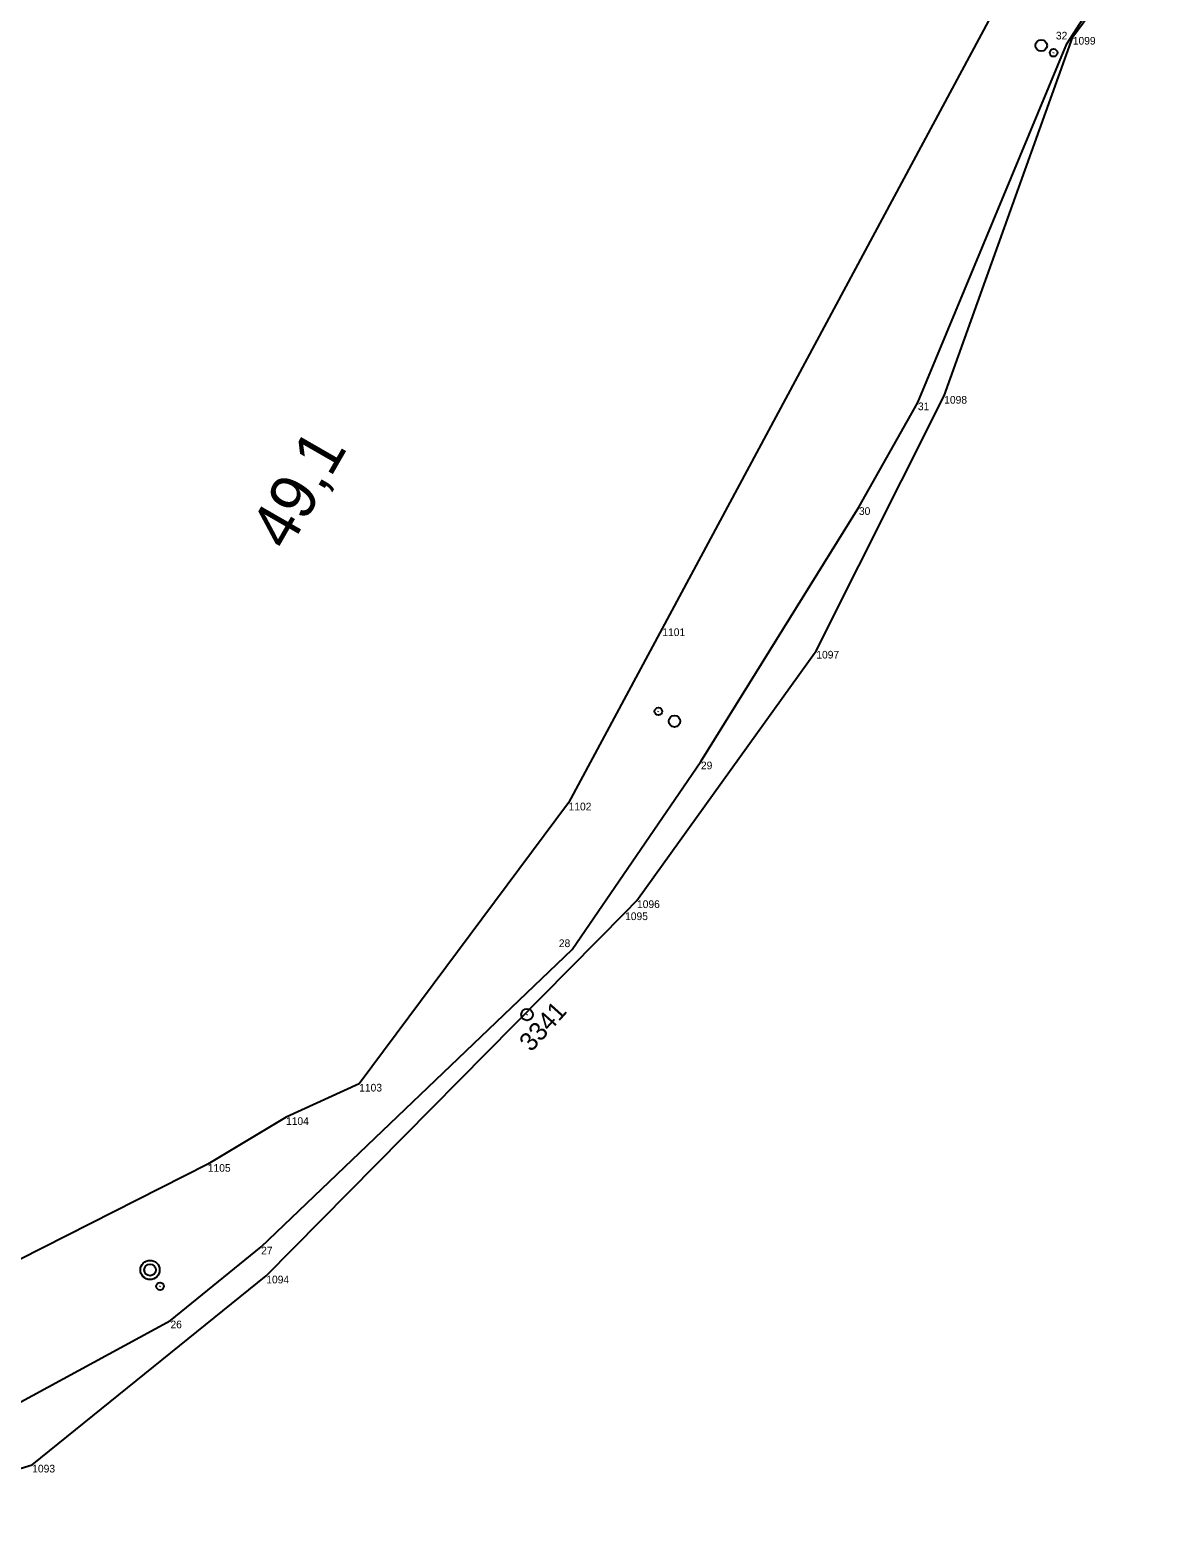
# Model space of a CAD drawing. Extents: x -678683 to -677755, y -1006946 to -1005971.
# Drawn here: x -678536.7 to -678391.2, y -1006829.9 to -1006633.5 of the extents above; entities that cross this region are included whole.
import ezdxf

# ---------------------------------------------------------------- set-up
doc = ezdxf.new("R2010")
doc.units = 0
for name, color, linetype in [('SSZT nové - lomové body', 7, 'Continuous'), ('SSZT_nové', 7, 'Continuous'), ('Stávající ŽBP', 7, 'Continuous'), ('SŽDC', 7, 'Continuous'), ('SŽDC - body', 7, 'Continuous'), ('Vrstva 7', 7, 'Continuous')]:
    doc.layers.add(name, color=color, linetype=linetype)

msp = doc.modelspace()

# ---------------------------------------------------------------- linework, layer by layer
at = {"layer": 'SSZT nové - lomové body'}
for p, q in [((-678401.67, -1006635.24), (-678401.67, -1006635.24)), ((-678421.07, -1006681.97), (-678421.07, -1006681.97)), ((-678428.75, -1006695.61), (-678428.75, -1006695.61)), ((-678449.33, -1006728.75), (-678449.33, -1006728.75)), ((-678466.12, -1006753.23), (-678466.12, -1006753.23)), ((-678506.62, -1006791.94), (-678506.62, -1006791.94)), ((-678518.43, -1006801.56), (-678518.43, -1006801.56))]:
    msp.add_line(p, q, dxfattribs=at)
at = {"layer": 'SSZT_nové'}
for points in [[(-678506.62, -1006791.94), (-678466.12, -1006753.23), (-678449.33, -1006728.75), (-678428.75, -1006695.61), (-678421.07, -1006681.97), (-678401.67, -1006635.24), (-678393.87, -1006623.11), (-678390.13, -1006617.26), (-678380, -1006603.76), (-678359.84, -1006584.7), (-678339.66, -1006565.68), (-678276.52, -1006503.93), (-678276.52, -1006503.93)], [(-678591.08, -1006829.86), (-678578.56, -1006827.33), (-678548.42, -1006815.94), (-678538.41, -1006812.42), (-678518.43, -1006801.56), (-678506.62, -1006791.94), (-678506.62, -1006791.94)]]:
    msp.add_lwpolyline(points, dxfattribs=at)
at = {"layer": 'Stávající ŽBP'}
msp.add_line((-678472.01, -1006761.74), (-678471.94, -1006761.66), dxfattribs=at)
msp.add_circle((-678471.98, -1006761.7), 0.756, dxfattribs=at)
at = {"layer": 'SŽDC'}
for p, q in [((-678400.89, -1006634.35), (-678396.04, -1006627.76)), ((-678411.85, -1006632.26), (-678454.36, -1006711.39)), ((-678417.64, -1006681.12), (-678400.89, -1006634.35)), ((-678434.3, -1006714.32), (-678417.64, -1006681.12)), ((-678454.36, -1006711.39), (-678466.57, -1006734.1)), ((-678457.66, -1006746.82), (-678434.3, -1006714.32)), ((-678466.57, -1006734.1), (-678493.85, -1006770.72)), ((-678505.95, -1006795.71), (-678459.21, -1006748.39)), ((-678459.21, -1006748.39), (-678457.66, -1006746.82)), ((-678493.85, -1006770.72), (-678503.38, -1006775.08)), ((-678503.38, -1006775.08), (-678513.57, -1006781.17)), ((-678513.57, -1006781.17), (-678541.67, -1006795.44)), ((-678536.44, -1006820.34), (-678505.95, -1006795.71)), ((-678542.33, -1006822.15), (-678536.44, -1006820.34))]:
    msp.add_line(p, q, dxfattribs=at)
at = {"layer": 'SŽDC - body'}
for p, q in [((-678400.89, -1006634.35), (-678400.89, -1006634.35)), ((-678417.64, -1006681.12), (-678417.64, -1006681.12)), ((-678454.36, -1006711.39), (-678454.36, -1006711.39)), ((-678434.3, -1006714.32), (-678434.3, -1006714.32)), ((-678466.57, -1006734.1), (-678466.57, -1006734.1)), ((-678459.21, -1006748.39), (-678459.21, -1006748.39)), ((-678457.66, -1006746.82), (-678457.66, -1006746.82)), ((-678493.85, -1006770.72), (-678493.85, -1006770.72)), ((-678503.38, -1006775.08), (-678503.38, -1006775.08)), ((-678513.57, -1006781.17), (-678513.57, -1006781.17)), ((-678505.95, -1006795.71), (-678505.95, -1006795.71)), ((-678536.44, -1006820.34), (-678536.44, -1006820.34))]:
    msp.add_line(p, q, dxfattribs=at)
at = {"layer": 'Vrstva 7'}
for p, q in [((-678403.41, -1006636.46), (-678403.36, -1006636.38)), ((-678454.89, -1006722.25), (-678454.84, -1006722.17)), ((-678519.82, -1006797.1), (-678519.73, -1006797.05))]:
    msp.add_line(p, q, dxfattribs=at)
for centre, radius in [((-678405, -1006635.46), 0.75), ((-678403.39, -1006636.42), 0.5), ((-678454.87, -1006722.21), 0.5), ((-678452.78, -1006723.49), 0.75), ((-678521.09, -1006794.96), 1.25), ((-678521.09, -1006794.96), 0.752), ((-678519.78, -1006797.08), 0.5)]:
    msp.add_circle(centre, radius, dxfattribs=at)

# ---------------------------------------------------------------- texts
at = {"layer": 'SSZT nové - lomové body'}
for s, p in [('32', (-678403.09, -1006634.68)), ('31', (-678421.07, -1006682.97)), ('30', (-678428.75, -1006696.61)), ('29', (-678449.33, -1006729.75)), ('28', (-678467.84, -1006752.91)), ('27', (-678506.62, -1006792.94)), ('26', (-678518.43, -1006802.56))]:
    msp.add_text(s, height=1, dxfattribs=at).set_placement(p)
at = {"layer": 'Stávající ŽBP'}
msp.add_text('3341', height=2.4, rotation=48.0148, dxfattribs=at).set_placement((-678471.44, -1006766.66))
at = {"layer": 'SŽDC - body'}
for s, p in [('1099', (-678400.89, -1006635.35)), ('1098', (-678417.64, -1006682.12)), ('1101', (-678454.36, -1006712.39)), ('1097', (-678434.3, -1006715.32)), ('1102', (-678466.57, -1006735.1)), ('1095', (-678459.21, -1006749.39)), ('1096', (-678457.66, -1006747.82)), ('1103', (-678493.85, -1006771.72)), ('1104', (-678503.38, -1006776.08)), ('1105', (-678513.57, -1006782.17)), ('1094', (-678505.95, -1006796.71)), ('1093', (-678536.44, -1006821.34))]:
    msp.add_text(s, height=1, dxfattribs=at).set_placement(p)
at = {"layer": 'Vrstva 7'}
msp.add_text('49,1', height=6, rotation=60.1002, dxfattribs=at).set_placement((-678503.14, -1006701.49))

doc.saveas('drawing.dxf')
